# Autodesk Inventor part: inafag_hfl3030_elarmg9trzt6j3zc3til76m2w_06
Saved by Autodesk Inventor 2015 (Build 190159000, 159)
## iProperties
Company: TraceParts S.A.
Created: 2012-12
Part Number: inafag_hfl3030_elarmg9trzt6j3zc3til76m2w_06
Checked By: TraceParts S.A.
Catalog Web Link: www.traceparts.com
Document SubType Name: Modeling
Designer: TraceParts
Material: Generic
Density: 1 g/cm^3
Appearance: Default
Author: TraceParts
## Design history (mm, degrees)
feature "inafag_hfl3030_elarmg9trzt6j3zc3til76m2w"
body "Solid1"
